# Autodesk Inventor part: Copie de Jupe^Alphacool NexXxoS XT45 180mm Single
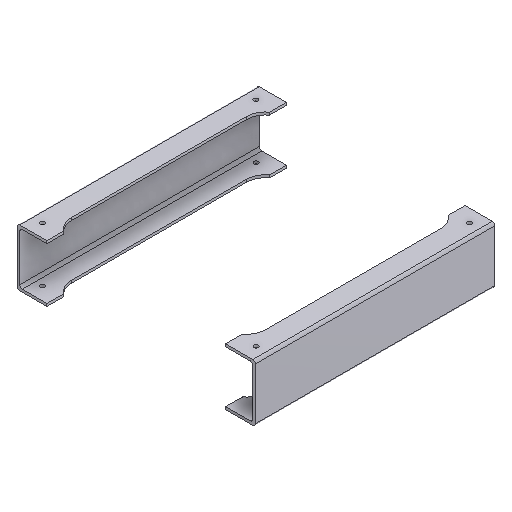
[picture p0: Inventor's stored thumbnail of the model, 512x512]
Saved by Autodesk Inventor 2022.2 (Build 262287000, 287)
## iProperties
Created: 2015-05
Part Number: Copie de Jupe^Alphacool NexXxoS XT45 180mm Single
Material: Generico
Document SubType Name: Modeling
Designer: 18907419
Density: 1 g/cm^3
Appearance: Default
Author: 18907419
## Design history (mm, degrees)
feature "Solido1"
feature "Solido2:1"
node "Solido2"
node "Solido3"
